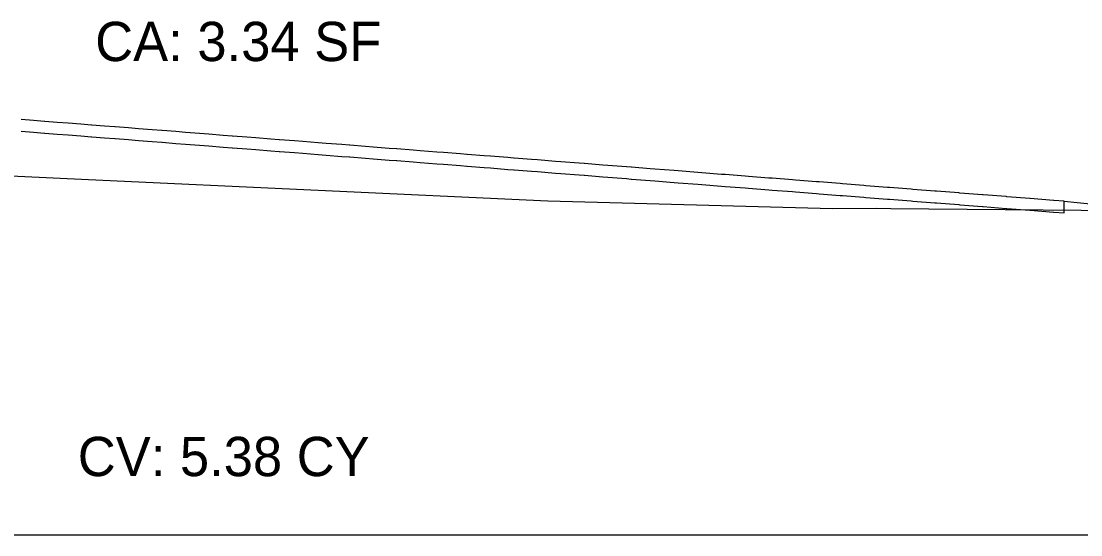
# Model space of a CAD drawing. Extents: x -100 to 4303, y -13 to 10775.
# Drawn here: x 211.18 to 256.51, y 1500 to 1521.95 of the extents above; entities that cross this region are included whole.
import ezdxf

# ---------------------------------------------------------------- set-up
doc = ezdxf.new("R2010")
doc.units = 0
for name, color, linetype in [('DTM_X_GROUND', 7, 'Continuous'), ('XS_CELL', 7, 'Continuous'), ('XS_SHEET_EW_TX_AREA', 7, 'Continuous'), ('XS_SHEET_EW_TX_VOLUME', 7, 'Continuous')]:
    doc.layers.add(name, color=color, linetype=linetype)

msp = doc.modelspace()

# ---------------------------------------------------------------- linework, layer by layer
at = {"layer": 'DTM_X_GROUND'}
for p, q in [((211.187, 1517.749), (211.18, 1517.749)), ((211.709, 1517.708), (211.187, 1517.749)), ((212.183, 1517.671), (211.709, 1517.708)), ((212.191, 1517.67), (212.183, 1517.671)), ((212.723, 1517.629), (212.191, 1517.67)), ((213.187, 1517.592), (212.723, 1517.629)), ((213.194, 1517.592), (213.187, 1517.592)), ((213.738, 1517.549), (213.194, 1517.592)), ((214.191, 1517.514), (213.738, 1517.549)), ((214.198, 1517.513), (214.191, 1517.514)), ((214.753, 1517.47), (214.198, 1517.513)), ((215.195, 1517.435), (214.753, 1517.47)), ((211.18, 1517.249), (211.187, 1517.249)), ((211.187, 1517.249), (211.709, 1517.208)), ((211.709, 1517.208), (212.183, 1517.171)), ((212.183, 1517.171), (212.191, 1517.17)), ((212.191, 1517.17), (212.723, 1517.129)), ((212.723, 1517.129), (213.187, 1517.092)), ((213.187, 1517.092), (213.194, 1517.092)), ((213.194, 1517.092), (213.738, 1517.049)), ((213.738, 1517.049), (214.191, 1517.014)), ((214.191, 1517.014), (214.198, 1517.013)), ((214.198, 1517.013), (214.753, 1516.97)), ((215.202, 1517.435), (215.195, 1517.435)), ((215.768, 1517.391), (215.202, 1517.435)), ((216.199, 1517.357), (215.768, 1517.391)), ((216.205, 1517.356), (216.199, 1517.357)), ((216.782, 1517.311), (216.205, 1517.356)), ((217.202, 1517.278), (216.782, 1517.311)), ((217.209, 1517.278), (217.202, 1517.278)), ((217.797, 1517.232), (217.209, 1517.278)), ((218.206, 1517.2), (217.797, 1517.232)), ((218.213, 1517.199), (218.206, 1517.2)), ((218.812, 1517.153), (218.213, 1517.199)), ((219.21, 1517.121), (218.812, 1517.153)), ((219.216, 1517.121), (219.21, 1517.121)), ((219.827, 1517.073), (219.216, 1517.121)), ((220.214, 1517.043), (219.827, 1517.073)), ((220.22, 1517.042), (220.214, 1517.043)), ((220.841, 1516.994), (220.22, 1517.042)), ((221.218, 1516.964), (220.841, 1516.994)), ((214.753, 1516.97), (215.195, 1516.935)), ((215.195, 1516.935), (215.202, 1516.935)), ((215.202, 1516.935), (215.768, 1516.891)), ((215.768, 1516.891), (216.199, 1516.857)), ((216.199, 1516.857), (216.205, 1516.856)), ((216.205, 1516.856), (216.782, 1516.811)), ((216.782, 1516.811), (217.202, 1516.778)), ((217.202, 1516.778), (217.209, 1516.778)), ((217.209, 1516.778), (217.797, 1516.732)), ((217.797, 1516.732), (218.206, 1516.7)), ((218.206, 1516.7), (218.213, 1516.699)), ((218.213, 1516.699), (218.812, 1516.653)), ((218.812, 1516.653), (219.21, 1516.621)), ((219.21, 1516.621), (219.216, 1516.621)), ((219.216, 1516.621), (219.827, 1516.573)), ((219.827, 1516.573), (220.214, 1516.543)), ((220.214, 1516.543), (220.22, 1516.542)), ((220.22, 1516.542), (220.841, 1516.494)), ((221.224, 1516.964), (221.218, 1516.964)), ((221.856, 1516.914), (221.224, 1516.964)), ((222.222, 1516.886), (221.856, 1516.914)), ((222.227, 1516.885), (222.222, 1516.886)), ((222.871, 1516.835), (222.227, 1516.885)), ((223.225, 1516.807), (222.871, 1516.835)), ((223.231, 1516.807), (223.225, 1516.807)), ((223.885, 1516.756), (223.231, 1516.807)), ((224.229, 1516.729), (223.885, 1516.756)), ((224.234, 1516.728), (224.229, 1516.729)), ((224.9, 1516.676), (224.234, 1516.728)), ((225.233, 1516.65), (224.9, 1516.676)), ((225.238, 1516.65), (225.233, 1516.65)), ((225.915, 1516.597), (225.238, 1516.65)), ((226.237, 1516.572), (225.915, 1516.597)), ((226.242, 1516.571), (226.237, 1516.572)), ((226.93, 1516.518), (226.242, 1516.571)), ((220.841, 1516.494), (221.218, 1516.464)), ((221.218, 1516.464), (221.224, 1516.464)), ((221.224, 1516.464), (221.856, 1516.414)), ((221.856, 1516.414), (222.222, 1516.386)), ((222.222, 1516.386), (222.227, 1516.385)), ((222.227, 1516.385), (222.871, 1516.335)), ((222.871, 1516.335), (223.225, 1516.307)), ((223.225, 1516.307), (223.231, 1516.307)), ((223.231, 1516.307), (223.885, 1516.256)), ((223.885, 1516.256), (224.229, 1516.229)), ((224.229, 1516.229), (224.234, 1516.228)), ((224.234, 1516.228), (224.9, 1516.176)), ((224.9, 1516.176), (225.233, 1516.15)), ((225.233, 1516.15), (225.238, 1516.15)), ((225.238, 1516.15), (225.915, 1516.097)), ((225.915, 1516.097), (226.237, 1516.072)), ((227.241, 1516.493), (226.93, 1516.518)), ((227.245, 1516.493), (227.241, 1516.493)), ((227.945, 1516.438), (227.245, 1516.493)), ((228.244, 1516.415), (227.945, 1516.438)), ((228.249, 1516.415), (228.244, 1516.415)), ((228.959, 1516.359), (228.249, 1516.415)), ((229.248, 1516.336), (228.959, 1516.359)), ((229.253, 1516.336), (229.248, 1516.336)), ((229.974, 1516.28), (229.253, 1516.336)), ((230.252, 1516.258), (229.974, 1516.28)), ((230.256, 1516.258), (230.252, 1516.258)), ((230.989, 1516.2), (230.256, 1516.258)), ((231.256, 1516.179), (230.989, 1516.2)), ((231.26, 1516.179), (231.256, 1516.179)), ((232.004, 1516.121), (231.26, 1516.179)), ((232.26, 1516.101), (232.004, 1516.121)), ((232.264, 1516.101), (232.26, 1516.101)), ((233.018, 1516.042), (232.264, 1516.101)), ((226.237, 1516.072), (226.242, 1516.071)), ((226.242, 1516.071), (226.93, 1516.018)), ((226.93, 1516.018), (227.241, 1515.993)), ((227.241, 1515.993), (227.245, 1515.993)), ((227.245, 1515.993), (227.945, 1515.938)), ((227.945, 1515.938), (228.244, 1515.915)), ((228.244, 1515.915), (228.249, 1515.915)), ((228.249, 1515.915), (228.959, 1515.859)), ((228.959, 1515.859), (229.248, 1515.836)), ((229.248, 1515.836), (229.253, 1515.836)), ((229.253, 1515.836), (229.974, 1515.78)), ((229.974, 1515.78), (230.252, 1515.758)), ((230.252, 1515.758), (230.256, 1515.758)), ((230.256, 1515.758), (230.989, 1515.7)), ((230.989, 1515.7), (231.256, 1515.679)), ((231.256, 1515.679), (231.26, 1515.679)), ((231.26, 1515.679), (232.004, 1515.621)), ((233.264, 1516.022), (233.018, 1516.042)), ((233.267, 1516.022), (233.264, 1516.022)), ((234.033, 1515.962), (233.267, 1516.022)), ((234.267, 1515.944), (234.033, 1515.962)), ((234.271, 1515.944), (234.267, 1515.944)), ((235.048, 1515.883), (234.271, 1515.944)), ((235.271, 1515.865), (235.048, 1515.883)), ((235.275, 1515.865), (235.271, 1515.865)), ((236.063, 1515.803), (235.275, 1515.865)), ((236.275, 1515.787), (236.063, 1515.803)), ((236.278, 1515.787), (236.275, 1515.787)), ((237.077, 1515.724), (236.278, 1515.787)), ((237.279, 1515.708), (237.077, 1515.724)), ((237.282, 1515.708), (237.279, 1515.708)), ((238.092, 1515.645), (237.282, 1515.708)), ((238.283, 1515.63), (238.092, 1515.645)), ((232.004, 1515.621), (232.26, 1515.601)), ((232.26, 1515.601), (232.264, 1515.601)), ((232.264, 1515.601), (233.018, 1515.542)), ((233.018, 1515.542), (233.264, 1515.522)), ((233.264, 1515.522), (233.267, 1515.522)), ((233.267, 1515.522), (234.033, 1515.462)), ((234.033, 1515.462), (234.267, 1515.444)), ((234.267, 1515.444), (234.271, 1515.444)), ((234.271, 1515.444), (235.048, 1515.383)), ((235.048, 1515.383), (235.271, 1515.365)), ((235.271, 1515.365), (235.275, 1515.365)), ((235.275, 1515.365), (236.063, 1515.303)), ((236.063, 1515.303), (236.275, 1515.287)), ((236.275, 1515.287), (236.278, 1515.287)), ((236.278, 1515.287), (237.077, 1515.224)), ((237.077, 1515.224), (237.279, 1515.208)), ((237.279, 1515.208), (237.282, 1515.208)), ((237.282, 1515.208), (238.092, 1515.145)), ((238.286, 1515.63), (238.283, 1515.63)), ((239.107, 1515.565), (238.286, 1515.63)), ((239.286, 1515.551), (239.107, 1515.565)), ((239.289, 1515.551), (239.286, 1515.551)), ((240.122, 1515.486), (239.289, 1515.551)), ((240.29, 1515.473), (240.122, 1515.486)), ((240.293, 1515.473), (240.29, 1515.473)), ((241.136, 1515.407), (240.293, 1515.473)), ((241.294, 1515.394), (241.136, 1515.407)), ((241.297, 1515.394), (241.294, 1515.394)), ((242.151, 1515.327), (241.297, 1515.394)), ((242.298, 1515.316), (242.151, 1515.327)), ((242.3, 1515.316), (242.298, 1515.316)), ((243.166, 1515.248), (242.3, 1515.316)), ((243.302, 1515.237), (243.166, 1515.248)), ((243.304, 1515.237), (243.302, 1515.237)), ((244.18, 1515.169), (243.304, 1515.237)), ((238.092, 1515.145), (238.283, 1515.13)), ((238.283, 1515.13), (238.286, 1515.13)), ((238.286, 1515.13), (239.107, 1515.065)), ((239.107, 1515.065), (239.286, 1515.051)), ((239.286, 1515.051), (239.289, 1515.051)), ((239.289, 1515.051), (240.122, 1514.986)), ((240.122, 1514.986), (240.29, 1514.973)), ((240.29, 1514.973), (240.293, 1514.973)), ((240.293, 1514.973), (241.136, 1514.907)), ((241.136, 1514.907), (241.294, 1514.894)), ((241.294, 1514.894), (241.297, 1514.894)), ((241.297, 1514.894), (242.151, 1514.827)), ((242.151, 1514.827), (242.298, 1514.816)), ((242.298, 1514.816), (242.3, 1514.816)), ((242.3, 1514.816), (243.166, 1514.748)), ((243.166, 1514.748), (243.302, 1514.737)), ((243.302, 1514.737), (243.304, 1514.737)), ((243.304, 1514.737), (244.18, 1514.669)), ((244.305, 1515.159), (244.18, 1515.169)), ((244.307, 1515.159), (244.305, 1515.159)), ((245.195, 1515.089), (244.307, 1515.159)), ((245.309, 1515.08), (245.195, 1515.089)), ((245.311, 1515.08), (245.309, 1515.08)), ((246.21, 1515.01), (245.311, 1515.08)), ((246.313, 1515.002), (246.21, 1515.01)), ((246.315, 1515.002), (246.313, 1515.002)), ((247.225, 1514.931), (246.315, 1515.002)), ((247.317, 1514.923), (247.225, 1514.931)), ((247.318, 1514.923), (247.317, 1514.923)), ((248.24, 1514.851), (247.318, 1514.923)), ((248.321, 1514.845), (248.24, 1514.851)), ((248.322, 1514.845), (248.321, 1514.845)), ((249.254, 1514.772), (248.322, 1514.845)), ((249.325, 1514.766), (249.254, 1514.772)), ((249.326, 1514.766), (249.325, 1514.766)), ((250.269, 1514.693), (249.326, 1514.766)), ((244.18, 1514.669), (244.305, 1514.659)), ((244.305, 1514.659), (244.307, 1514.659)), ((244.307, 1514.659), (245.195, 1514.589)), ((245.195, 1514.589), (245.309, 1514.58)), ((245.309, 1514.58), (245.311, 1514.58)), ((245.311, 1514.58), (246.21, 1514.51)), ((246.21, 1514.51), (246.313, 1514.502)), ((246.313, 1514.502), (246.315, 1514.502)), ((246.315, 1514.502), (247.225, 1514.431)), ((247.225, 1514.431), (247.317, 1514.423)), ((247.317, 1514.423), (247.318, 1514.423)), ((247.318, 1514.423), (248.24, 1514.351)), ((248.24, 1514.351), (248.321, 1514.345)), ((248.321, 1514.345), (248.322, 1514.345)), ((248.322, 1514.345), (249.254, 1514.272)), ((250.329, 1514.688), (250.269, 1514.693)), ((251.284, 1514.613), (250.329, 1514.688)), ((250.329, 1514.688), (250.329, 1514.688)), ((251.332, 1514.609), (251.284, 1514.613)), ((251.333, 1514.609), (251.332, 1514.609)), ((252.299, 1514.534), (251.333, 1514.609)), ((252.336, 1514.531), (252.299, 1514.534)), ((252.337, 1514.531), (252.336, 1514.531)), ((253.313, 1514.454), (252.337, 1514.531)), ((253.34, 1514.452), (253.313, 1514.454)), ((254.328, 1514.375), (253.34, 1514.452)), ((253.34, 1514.452), (253.34, 1514.452)), ((254.344, 1514.374), (254.328, 1514.375)), ((255.343, 1514.296), (254.344, 1514.374)), ((254.344, 1514.374), (254.344, 1514.374)), ((255.348, 1514.295), (255.343, 1514.296)), ((255.79, 1514.261), (255.348, 1514.295)), ((255.348, 1514.295), (255.348, 1514.295)), ((249.254, 1514.272), (249.325, 1514.266)), ((249.325, 1514.266), (249.326, 1514.266)), ((249.326, 1514.266), (250.269, 1514.193)), ((250.269, 1514.193), (250.329, 1514.188)), ((250.329, 1514.188), (250.329, 1514.188)), ((250.329, 1514.188), (251.284, 1514.113)), ((251.284, 1514.113), (251.332, 1514.109)), ((251.332, 1514.109), (251.333, 1514.109)), ((251.333, 1514.109), (252.299, 1514.034)), ((252.299, 1514.034), (252.336, 1514.031)), ((252.336, 1514.031), (252.337, 1514.031)), ((252.337, 1514.031), (253.313, 1513.954)), ((253.313, 1513.954), (253.34, 1513.952)), ((253.34, 1513.952), (253.34, 1513.952)), ((253.34, 1513.952), (254.328, 1513.875)), ((254.328, 1513.875), (254.344, 1513.874)), ((254.344, 1513.874), (254.344, 1513.874)), ((254.344, 1513.874), (255.343, 1513.796)), ((255.79, 1513.761), (255.79, 1514.261)), ((255.343, 1513.796), (255.348, 1513.795)), ((255.348, 1513.795), (255.348, 1513.795)), ((255.348, 1513.795), (255.79, 1513.761))]:
    msp.add_line(p, q, dxfattribs=at)
for points in [[(200.161, 1516.182), (209.501, 1515.398), (209.508, 1515.398), (214.069, 1515.192), (233.709, 1514.282), (245.883, 1513.954), (247.772, 1513.966), (248.38, 1513.947), (266.299, 1513.788), (292.07, 1513.357), (292.103, 1513.35), (300, 1513.32)], [(255.79, 1514.261), (256.351, 1514.203), (257.355, 1514.098), (258.359, 1513.994), (259.363, 1513.89), (260.367, 1513.786), (261.128, 1513.707)]]:
    msp.add_lwpolyline(points, dxfattribs=at)
at = {"layer": 'XS_CELL'}
msp.add_line((150, 1500), (300, 1500), dxfattribs=at)
msp.add_line((150, 1500), (300, 1500), dxfattribs=at)

# ---------------------------------------------------------------- texts
at = {"layer": 'XS_SHEET_EW_TX_AREA'}
msp.add_text('CA: 3.34 SF', height=1.68, dxfattribs=at).set_placement((214.35, 1520.248))
at = {"layer": 'XS_SHEET_EW_TX_VOLUME'}
msp.add_text('CV: 5.38 CY', height=1.68, dxfattribs=at).set_placement((213.604, 1502.507))

doc.saveas('drawing.dxf')
